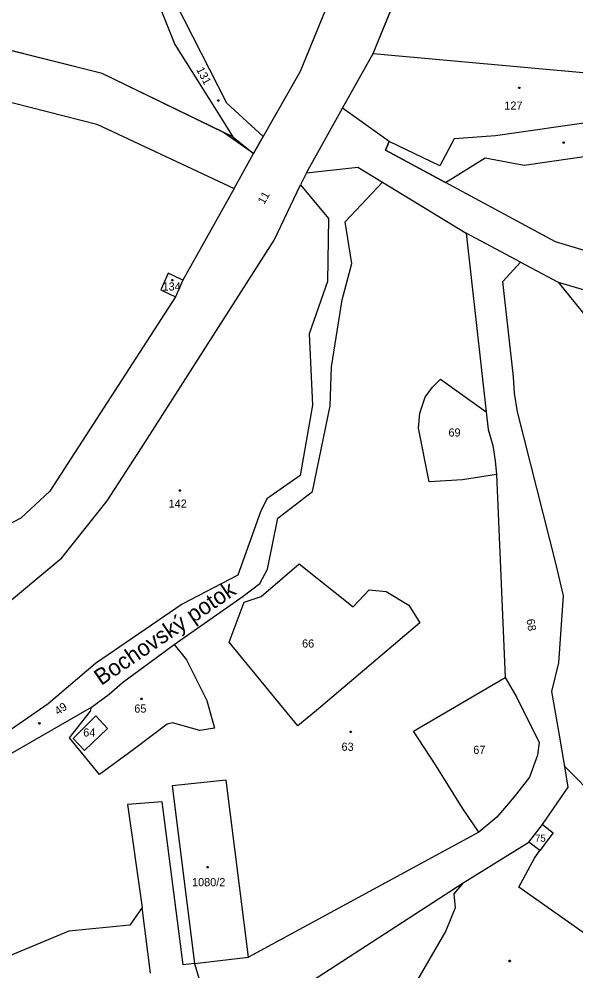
# Model space of a CAD drawing. Extents: x -841286 to -834997, y -1020681 to -1017810.
# Drawn here: x -838501.3 to -838385, y -1019173.8 to -1018975 of the extents above; entities that cross this region are included whole.
import ezdxf

# ---------------------------------------------------------------- set-up
doc = ezdxf.new("R2010")
doc.units = 0
for name, color, linetype in [('NERES_SET', 7, 'Continuous'), ('OVNE_POP', 7, 'Continuous'), ('OVNE_PRE', 7, 'Continuous'), ('OVNE_SET', 7, 'Continuous'), ('OVNI_PRE', 7, 'Continuous'), ('OVNI_SET', 7, 'Continuous')]:
    doc.layers.add(name, color=color, linetype=linetype)

msp = doc.modelspace()

# ---------------------------------------------------------------- linework, layer by layer
at = {"layer": 'OVNE_POP'}
for points in [[(-838396.75, -1018989.19), (-838396.66, -1018989.34), (-838396.75, -1018989.49), (-838396.93, -1018989.49), (-838397.02, -1018989.34), (-838396.93, -1018989.19)], [(-838459.51, -1018991.98), (-838459.58, -1018992.14), (-838459.76, -1018992.15), (-838459.85, -1018992), (-838459.78, -1018991.84), (-838459.6, -1018991.83)], [(-838387.66, -1019000.97), (-838387.77, -1019000.84), (-838387.7, -1019000.68), (-838387.52, -1019000.65), (-838387.41, -1019000.78), (-838387.48, -1019000.94)], [(-838467.63, -1019073.28), (-838467.54, -1019073.43), (-838467.63, -1019073.58), (-838467.81, -1019073.58), (-838467.9, -1019073.43), (-838467.81, -1019073.28)], [(-838475.63, -1019116.82), (-838475.54, -1019116.97), (-838475.63, -1019117.12), (-838475.81, -1019117.12), (-838475.9, -1019116.97), (-838475.81, -1019116.82)], [(-838497.03, -1019122.21), (-838497.19, -1019122.15), (-838497.2, -1019121.97), (-838497.05, -1019121.87), (-838496.89, -1019121.93), (-838496.88, -1019122.11)], [(-838431.97, -1019123.7), (-838431.88, -1019123.85), (-838431.97, -1019124), (-838432.15, -1019124), (-838432.24, -1019123.85), (-838432.15, -1019123.7)], [(-838398.75, -1019171.54), (-838398.66, -1019171.69), (-838398.75, -1019171.84), (-838398.93, -1019171.84), (-838399.02, -1019171.69), (-838398.93, -1019171.54)]]:
    msp.add_lwpolyline(points, close=True, dxfattribs=at)
at = {"layer": 'OVNE_SET'}
for p, q in [((-838427.33, -1018982.17), (-838371.86, -1018846.15)), ((-838411.01, -1018908.85), (-838442.62, -1018985.96)), ((-838483.95, -1018986.37), (-838555.51, -1018968.42)), ((-838471.67, -1018973.02), (-838468.75, -1018980.29)), ((-838457.9, -1018992.59), (-838468.55, -1018971.68)), ((-838468.75, -1018980.29), (-838460.49, -1018993.46)), ((-838433.75, -1018993.63), (-838427.33, -1018982.17)), ((-838427.33, -1018982.17), (-838361.96, -1018988.1)), ((-838534.71, -1018984.27), (-838485.02, -1018996.92)), ((-838456.64, -1018999.61), (-838483.95, -1018986.37)), ((-838442.62, -1018985.96), (-838450.34, -1018999.55)), ((-838450.34, -1018999.55), (-838457.9, -1018992.59)), ((-838460.49, -1018993.46), (-838456.64, -1018999.61)), ((-838441.29, -1019007.1), (-838433.75, -1018993.63)), ((-838424.03, -1019000.57), (-838433.75, -1018993.63)), ((-838370.67, -1018994.91), (-838401.78, -1018999.38)), ((-838485.02, -1018996.92), (-838456.37, -1019010.35)), ((-838456.64, -1018999.61), (-838452.31, -1019003.07)), ((-838452.31, -1019003.07), (-838450.34, -1018999.55)), ((-838424.03, -1019000.57), (-838424.76, -1019002.35)), ((-838413.4, -1019005.65), (-838424.03, -1019000.57)), ((-838410.44, -1019000.02), (-838413.4, -1019005.65)), ((-838401.78, -1018999.38), (-838410.44, -1019000.02)), ((-838395.82, -1019005.53), (-838359.47, -1019000.13)), ((-838456.37, -1019010.35), (-838452.31, -1019003.07)), ((-838424.76, -1019002.35), (-838412.23, -1019009.12)), ((-838412.23, -1019009.12), (-838403.97, -1019003.96)), ((-838403.97, -1019003.96), (-838395.82, -1019005.53)), ((-838441.29, -1019007.1), (-838442.49, -1019009.61)), ((-838441.29, -1019007.1), (-838430.54, -1019005.92)), ((-838430.54, -1019005.92), (-838425.39, -1019009.06)), ((-838433.2, -1019017.37), (-838425.39, -1019009.06)), ((-838425.39, -1019009.06), (-838407.94, -1019019.74)), ((-838389.31, -1019021.52), (-838412.23, -1019009.12)), ((-838456.37, -1019010.35), (-838467.07, -1019029.5)), ((-838447.99, -1019021.17), (-838442.49, -1019009.61)), ((-838442.49, -1019009.61), (-838436.66, -1019016.63)), ((-838436.66, -1019016.63), (-838436.91, -1019029.83)), ((-838431.83, -1019026.04), (-838433.2, -1019017.37)), ((-838396.58, -1019025.76), (-838407.94, -1019019.74)), ((-838407.94, -1019019.74), (-838403.73, -1019057.04)), ((-838474.97, -1019063.36), (-838447.99, -1019021.17)), ((-838360.67, -1019030.09), (-838389.31, -1019021.52)), ((-838433.8, -1019033.62), (-838431.83, -1019026.04)), ((-838400.26, -1019029.82), (-838396.58, -1019025.76)), ((-838396.58, -1019025.76), (-838388.73, -1019029.92)), ((-838470.16, -1019028.03), (-838471.7, -1019031.55)), ((-838467.07, -1019029.5), (-838470.16, -1019028.03)), ((-838467.07, -1019029.5), (-838468.61, -1019033.02)), ((-838436.91, -1019029.83), (-838440.72, -1019040.7)), ((-838398.07, -1019049.73), (-838400.26, -1019029.82)), ((-838388.73, -1019029.92), (-838365.99, -1019058.1)), ((-838388.73, -1019029.92), (-838352.34, -1019040.82)), ((-838468.61, -1019033.02), (-838494.88, -1019073.55)), ((-838471.7, -1019031.55), (-838468.61, -1019033.02)), ((-838436.04, -1019047.61), (-838433.8, -1019033.62)), ((-838440.72, -1019040.7), (-838440.01, -1019055.59)), ((-838436.31, -1019055.78), (-838436.04, -1019047.61)), ((-838414.96, -1019051.83), (-838413.26, -1019050.16)), ((-838413.26, -1019050.16), (-838403.73, -1019057.04)), ((-838397.87, -1019053.15), (-838398.07, -1019049.73)), ((-838416.47, -1019053.93), (-838414.96, -1019051.83)), ((-838417.6, -1019057.3), (-838416.47, -1019053.93)), ((-838397.22, -1019057.01), (-838397.87, -1019053.15)), ((-838440.01, -1019055.59), (-838442.56, -1019070.3)), ((-838440, -1019073.64), (-838436.31, -1019055.78)), ((-838417.86, -1019060.46), (-838417.6, -1019057.3)), ((-838403.73, -1019057.04), (-838403.32, -1019060.71)), ((-838389.17, -1019088.89), (-838397.22, -1019057.01)), ((-838415.67, -1019071.61), (-838417.86, -1019060.46)), ((-838403.32, -1019060.71), (-838402.34, -1019064.04)), ((-838482.92, -1019075.59), (-838474.97, -1019063.36)), ((-838402.34, -1019064.04), (-838401.87, -1019067.22)), ((-838401.87, -1019067.22), (-838401.58, -1019070.08)), ((-838442.56, -1019070.3), (-838449.56, -1019075.16)), ((-838401.58, -1019070.08), (-838408.71, -1019071.2)), ((-838401.58, -1019070.08), (-838399.78, -1019112.46)), ((-838408.71, -1019071.2), (-838415.67, -1019071.61)), ((-838494.88, -1019073.55), (-838500.9, -1019079.2)), ((-838447.28, -1019079.19), (-838440, -1019073.64)), ((-838492.37, -1019087.53), (-838482.92, -1019075.59)), ((-838449.56, -1019075.16), (-838450.86, -1019077.88)), ((-838450.86, -1019077.88), (-838455.58, -1019091.11)), ((-838500.9, -1019079.2), (-838530.43, -1019094.52)), ((-838449.41, -1019089.88), (-838447.28, -1019079.19)), ((-838508.62, -1019101.06), (-838492.37, -1019087.53)), ((-838450.98, -1019092.89), (-838449.41, -1019089.88)), ((-838450.75, -1019095.58), (-838442.79, -1019088.79)), ((-838442.79, -1019088.79), (-838431.54, -1019097.74)), ((-838387.58, -1019095.45), (-838389.17, -1019088.89)), ((-838455.58, -1019091.11), (-838467.26, -1019097.19)), ((-838454.47, -1019095.5), (-838450.98, -1019092.89)), ((-838431.54, -1019097.74), (-838428.19, -1019094.16)), ((-838428.19, -1019094.16), (-838424.67, -1019094.5)), ((-838424.67, -1019094.5), (-838419.92, -1019097.4)), ((-838468.89, -1019105.62), (-838454.47, -1019095.5)), ((-838454.28, -1019096.73), (-838450.75, -1019095.58)), ((-838388.57, -1019109.44), (-838387.58, -1019095.45)), ((-838467.26, -1019097.19), (-838485.32, -1019109.57)), ((-838457.44, -1019105.09), (-838454.28, -1019096.73)), ((-838419.92, -1019097.4), (-838417.61, -1019101.09)), ((-838417.61, -1019101.09), (-838439.18, -1019119.37)), ((-838479.69, -1019113.51), (-838468.89, -1019105.62)), ((-838468.89, -1019105.62), (-838466.3, -1019108.79)), ((-838443.08, -1019122.58), (-838457.44, -1019105.09)), ((-838485.32, -1019109.57), (-838495.22, -1019118.02)), ((-838466.3, -1019108.79), (-838462.1, -1019117.33)), ((-838390.03, -1019115.44), (-838388.57, -1019109.44)), ((-838418.9, -1019123.67), (-838399.78, -1019112.46)), ((-838399.78, -1019112.46), (-838397.35, -1019116.65)), ((-838482.47, -1019115.96), (-838479.69, -1019113.51)), ((-838486.15, -1019118.69), (-838482.47, -1019115.96)), ((-838388.49, -1019124.1), (-838390.03, -1019115.44)), ((-838495.22, -1019118.02), (-838504.75, -1019124.59)), ((-838462.1, -1019117.33), (-838460.51, -1019123.06)), ((-838397.35, -1019116.65), (-838392.68, -1019126.06)), ((-838504.89, -1019129.51), (-838486.15, -1019118.69)), ((-838490.73, -1019125.08), (-838486.37, -1019119.54)), ((-838486.37, -1019119.54), (-838486.15, -1019118.69)), ((-838439.18, -1019119.37), (-838443.08, -1019122.58)), ((-838488.05, -1019123.29), (-838485.27, -1019120.53)), ((-838485.27, -1019120.53), (-838482.81, -1019123.16)), ((-838470.38, -1019122.22), (-838477.18, -1019127.4)), ((-838469.25, -1019121.93), (-838470.38, -1019122.22)), ((-838463.52, -1019123.57), (-838469.25, -1019121.93)), ((-838489.97, -1019125.25), (-838488.05, -1019123.29)), ((-838482.81, -1019123.16), (-838487.63, -1019127.76)), ((-838460.51, -1019123.06), (-838463.52, -1019123.57)), ((-838414.35, -1019130.76), (-838418.9, -1019123.67)), ((-838387.36, -1019131.08), (-838388.49, -1019124.1)), ((-838484.51, -1019132.73), (-838490.73, -1019125.08)), ((-838487.63, -1019127.76), (-838489.97, -1019125.25)), ((-838392.68, -1019126.06), (-838393.06, -1019128.69)), ((-838477.18, -1019127.4), (-838484.51, -1019132.73)), ((-838393.06, -1019128.69), (-838394.68, -1019133.34)), ((-838412.63, -1019133.54), (-838414.35, -1019130.76)), ((-838364.28, -1019154.33), (-838387.36, -1019131.08)), ((-838386.66, -1019135.37), (-838387.36, -1019131.08)), ((-838458.01, -1019133.92), (-838469.34, -1019135.1)), ((-838453.39, -1019170.89), (-838458.01, -1019133.92)), ((-838408.72, -1019139.77), (-838412.63, -1019133.54)), ((-838394.68, -1019133.34), (-838397.88, -1019137.41)), ((-838469.34, -1019135.1), (-838464.64, -1019172.19)), ((-838392, -1019143.17), (-838386.66, -1019135.37)), ((-838397.88, -1019137.41), (-838401.54, -1019141.66)), ((-838471.43, -1019138.45), (-838478.63, -1019139.04)), ((-838478.63, -1019139.04), (-838475.59, -1019160.51)), ((-838467.02, -1019172.47), (-838471.43, -1019138.45)), ((-838405.27, -1019144.77), (-838408.72, -1019139.77)), ((-838401.54, -1019141.66), (-838405.27, -1019144.77)), ((-838394.85, -1019146.91), (-838392, -1019143.17)), ((-838392, -1019143.17), (-838389.78, -1019144.94)), ((-838405.27, -1019144.77), (-838453.39, -1019170.89)), ((-838389.78, -1019144.94), (-838392.56, -1019148.65)), ((-838408.56, -1019155.36), (-838394.85, -1019146.91)), ((-838392.56, -1019148.65), (-838394.85, -1019146.91)), ((-838396.97, -1019156.3), (-838393.67, -1019150.19)), ((-838393.67, -1019150.19), (-838392.56, -1019148.65)), ((-838448.35, -1019181.12), (-838408.56, -1019155.36)), ((-838408.56, -1019155.36), (-838410.48, -1019157.64)), ((-838410.48, -1019157.64), (-838410.22, -1019160.59)), ((-838374.59, -1019172.01), (-838396.97, -1019156.3)), ((-838475.59, -1019160.51), (-838478.16, -1019164.18)), ((-838473.87, -1019174.25), (-838475.59, -1019160.51)), ((-838410.22, -1019160.59), (-838412.17, -1019165.43)), ((-838478.16, -1019164.18), (-838490.88, -1019165.46)), ((-838490.88, -1019165.46), (-838504.29, -1019171.04)), ((-838412.17, -1019165.43), (-838418.77, -1019176.81)), ((-838464.64, -1019172.19), (-838453.39, -1019170.89)), ((-838464.64, -1019172.19), (-838467.02, -1019172.47)), ((-838464.64, -1019172.19), (-838457.71, -1019196.15))]:
    msp.add_line(p, q, dxfattribs=at)
at = {"layer": 'OVNI_PRE'}
for points in [[(-838469.18, -1019029.36), (-838469.09, -1019029.51), (-838469.18, -1019029.66), (-838469.36, -1019029.66), (-838469.45, -1019029.51), (-838469.36, -1019029.36)], [(-838461.82, -1019151.96), (-838461.73, -1019152.11), (-838461.82, -1019152.26), (-838462, -1019152.26), (-838462.09, -1019152.11), (-838462, -1019151.96)]]:
    msp.add_lwpolyline(points, close=True, dxfattribs=at)
at = {"layer": 'OVNI_SET'}
for points in [[(-838382.4, -1018842.66), (-838387.4, -1018854.73), (-838400.4, -1018885.65), (-838411.01, -1018908.85), (-838442.62, -1018985.96), (-838450.34, -1018999.55), (-838452.31, -1019003.07), (-838458.62, -1018998.65), (-838483.95, -1018986.37), (-838555.51, -1018968.42)], [(-838361.95, -1019029.71), (-838389.31, -1019021.52), (-838412.23, -1019009.12), (-838424.76, -1019002.35), (-838424.03, -1019000.57), (-838433.75, -1018993.63), (-838427.33, -1018982.17), (-838371.86, -1018846.15)]]:
    msp.add_lwpolyline(points, dxfattribs=at)

# ---------------------------------------------------------------- texts
at = {"layer": 'NERES_SET'}
msp.add_text('Bochovský potok', height=3.4, rotation=34.2056, dxfattribs=at).set_placement((-838484.14, -1019114.27))
at = {"layer": 'OVNE_PRE'}
for s, rotation, p in [('131', 297.9381, (-838464.33, -1018985.53)), ('11', 60.9054, (-838450.09, -1019013.82)), ('68', 279.4888, (-838395.36, -1019100.4)), ('49', 35.2369, (-838493.13, -1019120.42))]:
    msp.add_text(s, height=1.7, rotation=rotation, dxfattribs=at).set_placement(p)
for s, height, p in [('127', 1.7, (-838399.97, -1018993.92)), ('134', 1.7, (-838471.33, -1019031.69)), ('69', 1.7, (-838411.63, -1019062.18)), ('142', 1.7, (-838470.06, -1019077.03)), ('66', 1.7, (-838442.19, -1019106.24)), ('65', 1.7, (-838477.23, -1019119.83)), ('64', 1.7, (-838487.89, -1019124.82)), ('63', 1.7, (-838433.96, -1019127.81)), ('67', 1.7, (-838406.45, -1019128.44)), ('75', 1.5, (-838393.56, -1019146.8)), ('1080/2', 1.7, (-838465.17, -1019156.08))]:
    msp.add_text(s, height=height, dxfattribs=at).set_placement(p)

doc.saveas('drawing.dxf')
